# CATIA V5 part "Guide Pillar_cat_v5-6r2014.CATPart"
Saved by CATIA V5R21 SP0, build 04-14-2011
Part number: Guide Pillar
Bounding box of the stored display mesh (mm): x 82.5 to 107.5, y 17.5 to 42.5, z 0 to 200
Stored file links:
  D:\APS\CATIA V5-6R-2013-Project\CATIA V5-6R2013_partfiles\Tutorials\c12_catia_v5-6r2013_tut\c12tut2\Guide Pillar_cat_v5-6r2013.CATPart
  D:\APS\CATIA V5-6R-2013-Project\CATIA V5-6R2013_partfiles\Tutorials\c12_catia_v5-6r2013_tut\c12tut2\Assembly_cat_v5-6r2013.CATProduct
  D:\CATIA V5R21 E-RESOURCES\CATIA-V5R21\catia-v5r21-Tut\c12-catia-v5r21-tut\c12-catia-v5r21-tut02\Bottom Plate.CATPart
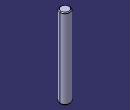
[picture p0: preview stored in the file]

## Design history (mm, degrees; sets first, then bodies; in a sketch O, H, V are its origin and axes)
Set1
  DatumSurface1: linked copy from another document
  DatumCurve1: linked copy from another document
Body1 (main body)
  Sketch1 on face of DatumSurface1, origin (0, 0, 0), H (1, 0, 0), V (0, 1, 0)
    projected circle E1 centre (95, 30) radius 12.5 from edge of DatumCurve1
  Pad1: profile Sketch1, direction (0, 0, 1), length 200
  Chamfer1: length 2, angle 45, on edge [face of Pad1 | face of Pad1] (x2)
